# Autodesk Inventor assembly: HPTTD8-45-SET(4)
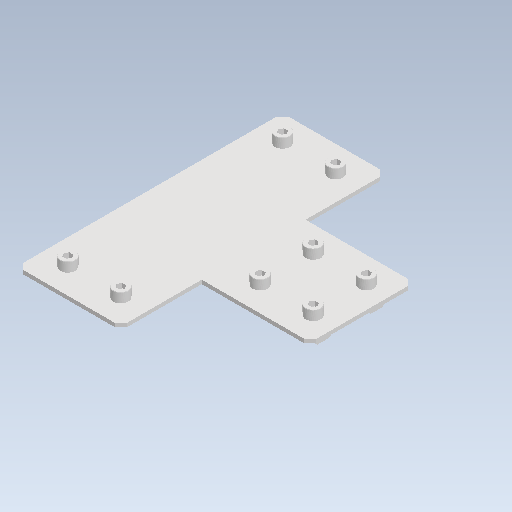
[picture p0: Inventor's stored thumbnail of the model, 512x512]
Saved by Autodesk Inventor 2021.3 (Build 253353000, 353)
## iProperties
Created: 2022-02
Part Number: HPTTD8-45-SET(4)
Document SubType Name: Assembly
Designer: kengo
Author: kengo
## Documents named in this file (4)
- C:\Users\kengo\Documents\S2S_frame\SDC345\frame_misumi_ver12\HPTTD8-45-SET(4).iam
- C:\Users\kengo\Documents\S2S_frame\SDC345\frame_misumi_ver12\HPTTD8-45.ipt
- C:\Users\kengo\Documents\S2S_frame\SDC345\frame_misumi_ver12\HNTT8-8.ipt
- C:\Users\kengo\Documents\S2S_frame\SDC345\frame_misumi_ver12\CBM8-15.ipt
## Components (17 placed, 3 different names)
1. HPTTD8-45
2. HNTT8-8
3. CBM8-15
4. HNTT8-8:1
5. CBM8-15:1
6. HNTT8-8:2
7. CBM8-15:2
8. HNTT8-8:3
9. CBM8-15:3
10. HNTT8-8:4
11. CBM8-15:4
12. HNTT8-8:5
13. CBM8-15:5
14. HNTT8-8:6
15. CBM8-15:6
16. HNTT8-8:7
17. CBM8-15:7
